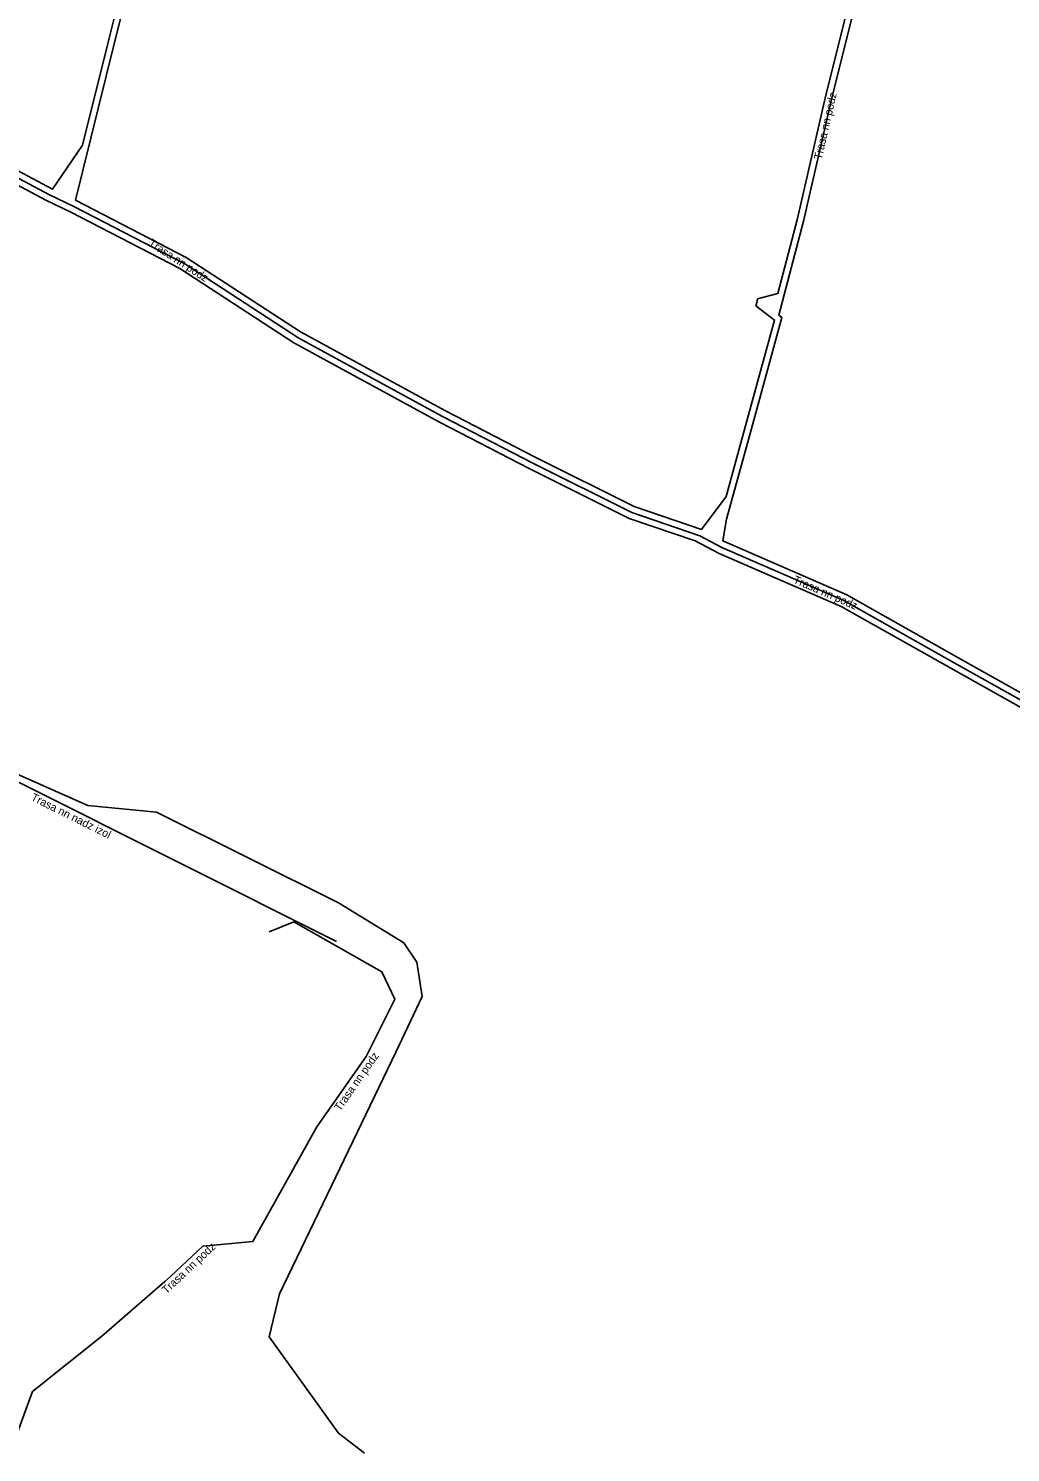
# Model space of a CAD drawing. Extents: x -528089 to -527692, y -1079306 to -1078676.
# Drawn here: x -527921.7 to -527860.3, y -1079080.7 to -1078991.7 of the extents above; entities that cross this region are included whole.
import ezdxf

# ---------------------------------------------------------------- set-up
doc = ezdxf.new("R2010")
doc.units = 0
for name, color, linetype in [('Popiskový text - Ostatní atributy Trasy', 7, 'Continuous'), ('Spojnice NN', 7, 'Continuous'), ('Spojnice VN', 7, 'Continuous')]:
    doc.layers.add(name, color=color, linetype=linetype)

msp = doc.modelspace()

# ---------------------------------------------------------------- linework, layer by layer
at = {"layer": 'Spojnice NN'}
for points in [[(-527951.407, -1078940.069), (-527951.36, -1078939.87), (-527951.313, -1078939.671), (-527949.788, -1078940.366), (-527951.605, -1078948.234), (-527953.536, -1078957.007), (-527955.859, -1078965.668), (-527955.735, -1078965.742), (-527956.995, -1078971.777), (-527958.27, -1078976.31), (-527958.608, -1078978.16), (-527954.781, -1078981.419), (-527943.291, -1078987.773), (-527937.17, -1078991.415), (-527930.886, -1078995.941), (-527923.94, -1078999.758), (-527920.173, -1079001.758), (-527918.304, -1078999.016), (-527916.724, -1078992.662), (-527915.621, -1078988.219), (-527916.874, -1078986.911)], [(-527911.19, -1078962.44), (-527911.142, -1078962.236), (-527908.999, -1078963.525), (-527913.797, -1078981.772), (-527915.399, -1078987.871), (-527915.179, -1078988.101), (-527916.336, -1078992.758), (-527918.744, -1079002.439), (-527911.818, -1079006.034), (-527904.685, -1079010.666), (-527895.612, -1079015.617), (-527890.019, -1079018.503), (-527883.825, -1079021.59), (-527879.628, -1079023.023), (-527878.088, -1079020.968), (-527876.743, -1079016.087), (-527875.059, -1079009.937), (-527876.22, -1079009.053), (-527876.17, -1079008.84)], [(-527870.38, -1078984.26), (-527870.33, -1078984.047), (-527868.774, -1078985.231), (-527871.466, -1078995.977), (-527873.256, -1079003.768), (-527874.794, -1079009.636), (-527874.601, -1079009.783), (-527876.357, -1079016.193), (-527878.06, -1079022.373), (-527878.284, -1079023.742), (-527870.541, -1079027.111), (-527863.644, -1079031.001), (-527858.148, -1079034.077), (-527853.503, -1079038.652), (-527849.874, -1079040.203), (-527844.274, -1079041.867), (-527838.885, -1079043.525), (-527837.548, -1079042.45), (-527836.162, -1079039.236), (-527835.067, -1079034.415), (-527836.052, -1079030.967)], [(-527876.17, -1079008.84), (-527876.118, -1079008.62), (-527874.854, -1079008.286), (-527873.644, -1079003.672), (-527871.854, -1078995.883), (-527869.226, -1078985.389), (-527870.43, -1078984.473), (-527870.38, -1078984.26)], [(-527924.32, -1079000.462), (-527920.587, -1079002.444), (-527919.025, -1079003.195), (-527912.221, -1079006.726), (-527905.095, -1079011.354), (-527895.987, -1079016.324), (-527890.381, -1079019.217), (-527884.134, -1079022.33), (-527880.009, -1079023.738), (-527878.509, -1079024.517), (-527870.898, -1079027.828), (-527864.036, -1079031.698), (-527858.633, -1079034.723)], [(-527858.39, -1079034.4), (-527863.84, -1079031.35), (-527870.72, -1079027.47), (-527878.35, -1079024.15), (-527879.724, -1079023.424), (-527883.98, -1079021.96), (-527890.115, -1079018.904), (-527895.8, -1079015.97), (-527904.781, -1079011.067), (-527911.914, -1079006.435), (-527918.84, -1079002.84), (-527920.4, -1079002.09), (-527924.13, -1079000.11)], [(-527932.259, -1079033.84), (-527902.433, -1079048.76)], [(-527906.629, -1079048.174), (-527905.086, -1079047.532), (-527899.59, -1079050.66), (-527898.78, -1079052.37), (-527900.57, -1079055.95), (-527903.65, -1079060.34), (-527907.65, -1079067.51), (-527909.205, -1079067.654)], [(-527909.205, -1079067.654), (-527910.78, -1079067.8), (-527912.78, -1079069.674)], [(-527912.78, -1079069.674), (-527913.15, -1079070.02), (-527917.1, -1079073.42), (-527921.413, -1079076.892), (-527922.586, -1079080.074), (-527924.86, -1079085.77), (-527925.354, -1079085.808), (-527927.982, -1079090.177), (-527929.045, -1079092.173), (-527929.487, -1079092.011), (-527931.27, -1079094.63), (-527929.212, -1079098.88), (-527928.094, -1079103.067), (-527930.429, -1079103.322)]]:
    msp.add_lwpolyline(points, dxfattribs=at)
at = {"layer": 'Spojnice VN'}
msp.add_lwpolyline([(-527900.67, -1079080.75), (-527902.31, -1079079.5), (-527906.63, -1079073.48), (-527905.99, -1079070.78), (-527898.71, -1079055.64), (-527897.08, -1079052.2), (-527897.4, -1079050.06), (-527898.22, -1079048.86), (-527902.3, -1079046.36), (-527913.68, -1079040.68), (-527917.97, -1079040.28), (-527925.59, -1079036.9), (-527939.41, -1079029.3), (-527955.66, -1079020.73), (-527960.68, -1079017.89), (-527978.24, -1079008.97), (-527990.68, -1079001.77), (-528000.14, -1078996.92), (-528007.17, -1078993.13)], dxfattribs=at)
msp.add_lwpolyline([(-527900.67, -1079080.75), (-527902.31, -1079079.5), (-527906.63, -1079073.48), (-527905.99, -1079070.78), (-527898.71, -1079055.64), (-527897.08, -1079052.2), (-527897.4, -1079050.06), (-527898.22, -1079048.86), (-527902.3, -1079046.36), (-527913.68, -1079040.68), (-527917.97, -1079040.28), (-527925.59, -1079036.9), (-527939.41, -1079029.3), (-527955.66, -1079020.73), (-527960.68, -1079017.89), (-527978.24, -1079008.97), (-527990.68, -1079001.77), (-528000.14, -1078996.92), (-528007.17, -1078993.13)], dxfattribs=at)

# ---------------------------------------------------------------- texts
at = {"layer": 'Popiskový text - Ostatní atributy Trasy'}
for s, rotation, p in [('Trasa nn podz', 77.05751, (-527872.121, -1078999.947)), ('Trasa nn podz', 327.00127, (-527914.226, -1079005.245)), ('Trasa nn podz', 336.48601, (-527873.932, -1079026.344)), ('Trasa nn nadz izol', 333.42419, (-527921.563, -1079039.918)), ('Trasa nn podz', 54.94671, (-527902.203, -1079059.409)), ('Trasa nn podz', 43.12999, (-527913.055, -1079070.822))]:
    msp.add_text(s, height=0.5, rotation=rotation, dxfattribs=at).set_placement(p)

doc.saveas('drawing.dxf')
